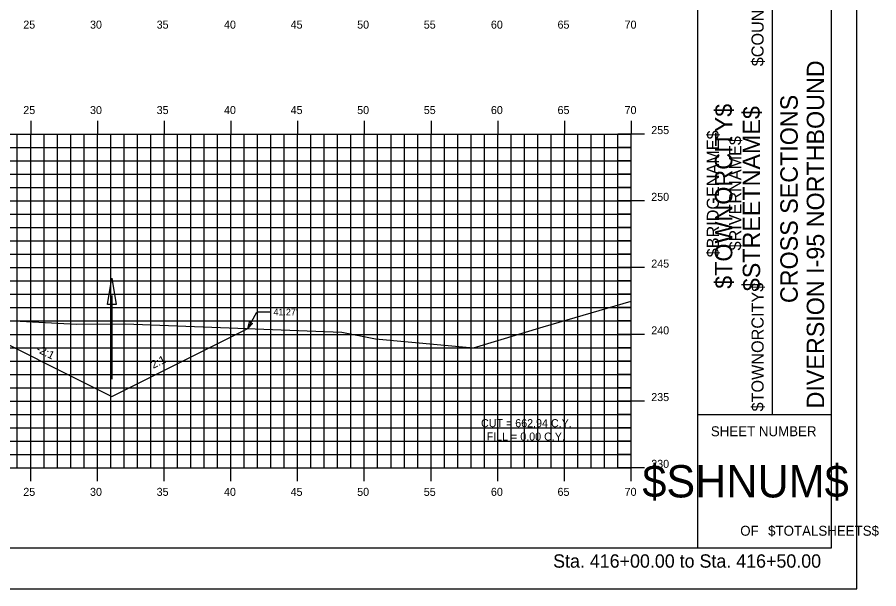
# Model space of a CAD drawing. Extents: x 1160718 to 1173142, y 616002 to 617630.
# Drawn here: x 1168655.8 to 1168720.4, y 616613.9 to 616656.7 of the extents above; entities that cross this region are included whole.
import ezdxf

# ---------------------------------------------------------------- set-up
doc = ezdxf.new("R2010")
doc.units = 0
for name, color, linetype in [('ANNOTATION', 7, 'Continuous'), ('BORDER', 7, 'Continuous'), ('BRIDGE_TITLE', 7, 'Continuous'), ('D_Drainage_Ditch_Line', 7, 'Continuous'), ('D_Roadway_SlopeLines', 7, 'Continuous'), ('H_V ANNOTATION', 7, 'Continuous'), ('HIGHWAY_TITLE', 7, 'Continuous'), ('MAJOR', 7, 'Continuous'), ('MINOR', 7, 'Continuous'), ('PLOT BOUNDARY', 7, 'Continuous'), ('S_Roadway_Centerline', 7, 'Continuous')]:
    doc.layers.add(name, color=color, linetype=linetype)

msp = doc.modelspace()

# ---------------------------------------------------------------- linework, layer by layer
at = {"layer": 'ANNOTATION'}
for p in [(1168673.124, 616633.364), (1168674.8, 616634.598)]:
    msp.add_line(p, (1168673.8, 616634.598), dxfattribs=at)
msp.add_lwpolyline([(1168673.473, 616633.742), (1168673.124, 616633.364), (1168673.254, 616633.863)], close=True, dxfattribs=at)
at = {"layer": 'BORDER'}
for p, q in [((1168706.855, 616616.931), (1168706.855, 616721.931)), ((1168716.855, 616616.931), (1168716.855, 616721.931)), ((1168712.446, 616626.931), (1168712.446, 616661.931)), ((1168706.855, 616626.931), (1168716.855, 616626.931)), ((1168556.855, 616616.928), (1168716.855, 616616.928))]:
    msp.add_line(p, q, dxfattribs=at)
at = {"layer": 'D_Drainage_Ditch_Line'}
msp.add_line((1168662.935, 616635.825), (1168662.934, 616629.582), dxfattribs=at)
msp.add_lwpolyline([(1168663.263, 616635.169), (1168662.607, 616635.169), (1168662.935, 616637.137)], close=True, dxfattribs=at)
at = {"layer": 'D_Roadway_SlopeLines'}
for points in [[(1168651.852, 616633.811), (1168662.934, 616628.269)], [(1168662.934, 616628.269), (1168673.124, 616633.364)]]:
    msp.add_lwpolyline(points, dxfattribs=at)
at = {"layer": 'MAJOR'}
for p, q in [((1168656.855, 616648.93), (1168656.855, 616647.928)), ((1168661.855, 616648.93), (1168661.855, 616647.928)), ((1168666.855, 616648.93), (1168666.855, 616647.928)), ((1168671.855, 616648.93), (1168671.855, 616647.928)), ((1168676.855, 616648.93), (1168676.855, 616647.928)), ((1168681.855, 616648.93), (1168681.855, 616647.928)), ((1168686.855, 616648.93), (1168686.855, 616647.928)), ((1168691.855, 616648.93), (1168691.855, 616647.928)), ((1168696.855, 616648.93), (1168696.855, 616647.928)), ((1168701.855, 616648.93), (1168701.855, 616647.928)), ((1168561.855, 616647.928), (1168701.855, 616647.928)), ((1168561.855, 616647.928), (1168701.855, 616647.928)), ((1168656.855, 616622.928), (1168656.855, 616647.928)), ((1168661.855, 616622.928), (1168661.855, 616647.928)), ((1168666.855, 616622.928), (1168666.855, 616647.928)), ((1168671.855, 616622.928), (1168671.855, 616647.928)), ((1168676.855, 616622.928), (1168676.855, 616647.928)), ((1168681.855, 616622.928), (1168681.855, 616647.928)), ((1168686.855, 616622.928), (1168686.855, 616647.928)), ((1168691.855, 616622.928), (1168691.855, 616647.928)), ((1168696.855, 616622.928), (1168696.855, 616647.928)), ((1168702.857, 616647.928), (1168700.853, 616647.928)), ((1168701.855, 616622.928), (1168701.855, 616647.928)), ((1168701.855, 616622.928), (1168701.855, 616647.928)), ((1168561.855, 616642.928), (1168701.855, 616642.928)), ((1168702.857, 616642.928), (1168700.853, 616642.928)), ((1168561.855, 616637.928), (1168701.855, 616637.928)), ((1168702.857, 616637.928), (1168700.853, 616637.928)), ((1168561.855, 616632.928), (1168701.855, 616632.928)), ((1168702.857, 616632.928), (1168700.853, 616632.928)), ((1168561.855, 616627.928), (1168701.855, 616627.928)), ((1168702.857, 616627.928), (1168700.853, 616627.928)), ((1168561.855, 616622.928), (1168701.855, 616622.928)), ((1168561.855, 616622.928), (1168701.855, 616622.928)), ((1168656.855, 616621.926), (1168656.855, 616622.928)), ((1168661.855, 616621.926), (1168661.855, 616622.928)), ((1168666.855, 616621.926), (1168666.855, 616622.928)), ((1168671.855, 616621.926), (1168671.855, 616622.928)), ((1168676.855, 616621.926), (1168676.855, 616622.928)), ((1168681.855, 616621.926), (1168681.855, 616622.928)), ((1168686.855, 616621.926), (1168686.855, 616622.928)), ((1168691.855, 616621.926), (1168691.855, 616622.928)), ((1168696.855, 616621.926), (1168696.855, 616622.928)), ((1168702.857, 616622.928), (1168700.853, 616622.928)), ((1168701.855, 616621.926), (1168701.855, 616622.928))]:
    msp.add_line(p, q, dxfattribs=at)
at = {"layer": 'MINOR'}
for p, q in [((1168655.855, 616622.928), (1168655.855, 616647.928)), ((1168657.855, 616622.928), (1168657.855, 616647.928)), ((1168658.855, 616622.928), (1168658.855, 616647.928)), ((1168659.855, 616622.928), (1168659.855, 616647.928)), ((1168660.855, 616622.928), (1168660.855, 616647.928)), ((1168662.855, 616622.928), (1168662.855, 616647.928)), ((1168663.855, 616622.928), (1168663.855, 616647.928)), ((1168664.855, 616622.928), (1168664.855, 616647.928)), ((1168665.855, 616622.928), (1168665.855, 616647.928)), ((1168667.855, 616622.928), (1168667.855, 616647.928)), ((1168668.855, 616622.928), (1168668.855, 616647.928)), ((1168669.855, 616622.928), (1168669.855, 616647.928)), ((1168670.855, 616622.928), (1168670.855, 616647.928)), ((1168672.855, 616622.928), (1168672.855, 616647.928)), ((1168673.855, 616622.928), (1168673.855, 616647.928)), ((1168674.855, 616622.928), (1168674.855, 616647.928)), ((1168675.855, 616622.928), (1168675.855, 616647.928)), ((1168677.855, 616622.928), (1168677.855, 616647.928)), ((1168678.855, 616622.928), (1168678.855, 616647.928)), ((1168679.855, 616622.928), (1168679.855, 616647.928)), ((1168680.855, 616622.928), (1168680.855, 616647.928)), ((1168682.855, 616622.928), (1168682.855, 616647.928)), ((1168683.855, 616622.928), (1168683.855, 616647.928)), ((1168684.855, 616622.928), (1168684.855, 616647.928)), ((1168685.855, 616622.928), (1168685.855, 616647.928)), ((1168687.855, 616622.928), (1168687.855, 616647.928)), ((1168688.855, 616622.928), (1168688.855, 616647.928)), ((1168689.855, 616622.928), (1168689.855, 616647.928)), ((1168690.855, 616622.928), (1168690.855, 616647.928)), ((1168692.855, 616622.928), (1168692.855, 616647.928)), ((1168693.855, 616622.928), (1168693.855, 616647.928)), ((1168694.855, 616622.928), (1168694.855, 616647.928)), ((1168695.855, 616622.928), (1168695.855, 616647.928)), ((1168697.855, 616622.928), (1168697.855, 616647.928)), ((1168698.855, 616622.928), (1168698.855, 616647.928)), ((1168699.855, 616622.928), (1168699.855, 616647.928)), ((1168700.855, 616622.928), (1168700.855, 616647.928)), ((1168561.855, 616646.928), (1168701.855, 616646.928)), ((1168701.855, 616646.928), (1168700.853, 616646.928)), ((1168561.855, 616645.928), (1168701.855, 616645.928)), ((1168701.855, 616645.928), (1168700.853, 616645.928)), ((1168561.855, 616644.928), (1168701.855, 616644.928)), ((1168701.855, 616644.928), (1168700.853, 616644.928)), ((1168561.855, 616643.928), (1168701.855, 616643.928)), ((1168701.855, 616643.928), (1168700.853, 616643.928)), ((1168561.855, 616641.928), (1168701.855, 616641.928)), ((1168701.855, 616641.928), (1168700.853, 616641.928)), ((1168561.855, 616640.928), (1168701.855, 616640.928)), ((1168701.855, 616640.928), (1168700.853, 616640.928)), ((1168561.855, 616639.928), (1168701.855, 616639.928)), ((1168701.855, 616639.928), (1168700.853, 616639.928)), ((1168561.855, 616638.928), (1168701.855, 616638.928)), ((1168701.855, 616638.928), (1168700.853, 616638.928)), ((1168561.855, 616636.928), (1168701.855, 616636.928)), ((1168701.855, 616636.928), (1168700.853, 616636.928)), ((1168561.855, 616635.928), (1168701.855, 616635.928)), ((1168701.855, 616635.928), (1168700.853, 616635.928)), ((1168561.855, 616634.928), (1168701.855, 616634.928)), ((1168701.855, 616634.928), (1168700.853, 616634.928)), ((1168561.855, 616633.928), (1168701.855, 616633.928)), ((1168701.855, 616633.928), (1168700.853, 616633.928)), ((1168561.855, 616631.928), (1168701.855, 616631.928)), ((1168701.855, 616631.928), (1168700.853, 616631.928)), ((1168561.855, 616630.928), (1168701.855, 616630.928)), ((1168701.855, 616630.928), (1168700.853, 616630.928)), ((1168561.855, 616629.928), (1168701.855, 616629.928)), ((1168701.855, 616629.928), (1168700.853, 616629.928)), ((1168561.855, 616628.928), (1168701.855, 616628.928)), ((1168701.855, 616628.928), (1168700.853, 616628.928)), ((1168561.855, 616626.928), (1168701.855, 616626.928)), ((1168701.855, 616626.928), (1168700.853, 616626.928)), ((1168561.855, 616625.928), (1168701.855, 616625.928)), ((1168701.855, 616625.928), (1168700.853, 616625.928)), ((1168561.855, 616624.928), (1168701.855, 616624.928)), ((1168701.855, 616624.928), (1168700.853, 616624.928)), ((1168561.855, 616623.928), (1168701.855, 616623.928)), ((1168701.855, 616623.928), (1168700.853, 616623.928))]:
    msp.add_line(p, q, dxfattribs=at)
at = {"layer": 'PLOT BOUNDARY'}
msp.add_lwpolyline([(1168548.762, 616613.869), (1168718.762, 616613.869), (1168718.762, 616723.869), (1168548.762, 616723.869)], close=True, dxfattribs=at)
at = {"layer": 'S_Roadway_Centerline'}
msp.add_lwpolyline([(1168561.855, 616640.999), (1168573.256, 616637.851), (1168582.484, 616637.544), (1168601.11, 616636.614), (1168610.042, 616636.052), (1168613.568, 616635.849), (1168628.287, 616635.249), (1168635.625, 616634.973), (1168638.216, 616634.864), (1168660.285, 616633.7), (1168663.944, 616633.708), (1168680.168, 616633.1), (1168682.699, 616632.581), (1168690.038, 616631.906), (1168695.255, 616633.481), (1168701.855, 616635.415)], dxfattribs=at)

# ---------------------------------------------------------------- texts
at = {"layer": 'ANNOTATION'}
msp.add_text("41.27'", height=0.5, dxfattribs=at).set_placement((1168675.05, 616634.348))
for s, rotation, p in [('-2:1', 333.43495, (1168657.216, 616631.646)), ('2:1', 26.56505, (1168666.043, 616630.342)), ('CUT = 662.94 C.Y.', 359.92408, (1168690.599, 616625.979)), ('FILL = 0.00 C.Y.', 359.92408, (1168691.021, 616624.976))]:
    msp.add_text(s, height=0.6, rotation=rotation, dxfattribs=at).set_placement(p)
at = {"layer": 'BORDER'}
for s, height, rotation, p in [('DIVERSION I-95 NORTHBOUND  ', 1.30428, 90, (1168716.309, 616627.379)), ('CROSS SECTIONS', 1.30428, 90, (1168714.331, 616635.27)), ('SHEET NUMBER', 0.74527, 360, (1168707.82, 616625.295)), ('$SHNUM$', 2.4194, 360, (1168702.688, 616620.711)), ('OF', 0.7453, 360, (1168710.022, 616617.841)), ('$TOTALSHEETS$', 0.74527, 360, (1168712.111, 616617.841))]:
    msp.add_text(s, height=height, rotation=rotation, dxfattribs=at).set_placement(p)
at = {"layer": 'BRIDGE_TITLE'}
for s, height, p in [('$COUNTY$', 0.9072, (1168711.775, 616653.011)), ('$BRIDGENAME$', 0.90716, (1168708.421, 616638.7)), ('$RIVERNAME$', 0.90716, (1168710.098, 616639.214)), ('$TOWNORCITY$', 0.90716, (1168711.775, 616627.152))]:
    msp.add_text(s, height=height, rotation=90, dxfattribs=at).set_placement(p)
at = {"layer": 'H_V ANNOTATION'}
for s, height, p in [('25', 0.6, (1168656.301, 616655.828)), ('30', 0.6, (1168661.303, 616655.828)), ('35', 0.6, (1168666.295, 616655.828)), ('40', 0.6, (1168671.341, 616655.828)), ('45', 0.6, (1168676.333, 616655.828)), ('50', 0.6, (1168681.319, 616655.828)), ('55', 0.6, (1168686.311, 616655.828)), ('60', 0.6, (1168691.341, 616655.828)), ('65', 0.6, (1168696.333, 616655.828)), ('70', 0.6, (1168701.357, 616655.828)), ('25', 0.6, (1168656.301, 616649.428)), ('30', 0.6, (1168661.303, 616649.428)), ('35', 0.6, (1168666.295, 616649.428)), ('40', 0.6, (1168671.341, 616649.428)), ('45', 0.6, (1168676.333, 616649.428)), ('50', 0.6, (1168681.319, 616649.428)), ('55', 0.6, (1168686.311, 616649.428)), ('60', 0.6, (1168691.341, 616649.428)), ('65', 0.6, (1168696.333, 616649.428)), ('70', 0.6, (1168701.357, 616649.428)), ('255', 0.6, (1168703.355, 616647.928)), ('250', 0.6, (1168703.355, 616642.928)), ('245', 0.6, (1168703.355, 616637.928)), ('240', 0.6, (1168703.355, 616632.928)), ('235', 0.6, (1168703.355, 616627.928)), ('230', 0.6, (1168703.355, 616622.928)), ('25', 0.6, (1168656.301, 616620.828)), ('30', 0.6, (1168661.303, 616620.828)), ('35', 0.6, (1168666.295, 616620.828)), ('40', 0.6, (1168671.341, 616620.828)), ('45', 0.6, (1168676.333, 616620.828)), ('50', 0.6, (1168681.319, 616620.828)), ('55', 0.6, (1168686.311, 616620.828)), ('60', 0.6, (1168691.341, 616620.828)), ('65', 0.6, (1168696.333, 616620.828)), ('70', 0.6, (1168701.357, 616620.828)), ('Sta. 416+00.00 to Sta. 416+50.00', 1.0002, (1168696.001, 616615.448))]:
    msp.add_text(s, height=height, dxfattribs=at).set_placement(p)
at = {"layer": 'HIGHWAY_TITLE'}
for s, p in [('$TOWNORCITY$', (1168709.427, 616636.34)), ('$STREETNAME$', (1168711.514, 616636.16))]:
    msp.add_text(s, height=1.30428, rotation=90, dxfattribs=at).set_placement(p)

doc.saveas('drawing.dxf')
